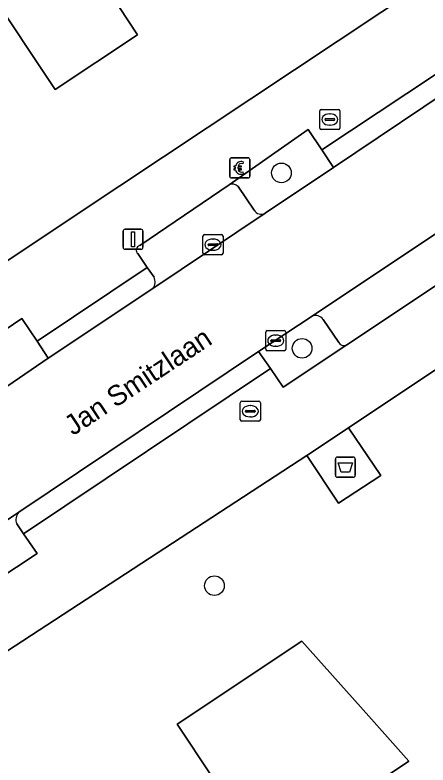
# Model space of a CAD drawing. Extents: x 161347 to 161881, y 382161 to 382804.
# Drawn here: x 161574.44 to 161594.98, y 382587.37 to 382624.69 of the extents above; entities that cross this region are included whole.
import ezdxf

# ---------------------------------------------------------------- set-up
doc = ezdxf.new("R2010")
doc.units = 0
for name, color, linetype in [('IMGEO_Afval_apart_plaats', 7, 'Continuous'), ('IMGEO_Betaalautomaat', 7, 'Continuous'), ('IMGEO_Boom', 7, 'Continuous'), ('IMGEO_Brandkraan', 7, 'Continuous'), ('IMGEO_Erf', 7, 'Continuous'), ('IMGEO_Groenvoorziening', 7, 'Continuous'), ('IMGEO_Kolk', 7, 'Continuous'), ('IMGEO_Lichtmast', 7, 'Continuous'), ('IMGEO_Openbare_ruimte_label', 7, 'Continuous'), ('IMGEO_Pand', 7, 'Continuous'), ('IMGEO_Parkeervlak_open', 7, 'Continuous'), ('IMGEO_Rijbaan_lokaal_open', 7, 'Continuous'), ('IMGEO_Rioolput', 7, 'Continuous'), ('IMGEO_Voetpad_gesloten', 7, 'Continuous'), ('IMGEO_Voetpad_open', 7, 'Continuous')]:
    doc.layers.add(name, color=color, linetype=linetype)

msp = doc.modelspace()

# ---------------------------------------------------------------- linework, layer by layer
at = {"layer": 'IMGEO_Afval_apart_plaats'}
for p, q in [((161590.47, 382602.687), (161591.26, 382602.687)), ((161591.26, 382602.687), (161590.47, 382602.687)), ((161590.37, 382601.787), (161590.37, 382602.587)), ((161590.37, 382602.587), (161590.37, 382601.787)), ((161591.36, 382602.587), (161591.36, 382601.787)), ((161591.36, 382601.787), (161591.36, 382602.587)), ((161591.26, 382601.687), (161590.47, 382601.687)), ((161590.47, 382601.687), (161591.26, 382601.687))]:
    msp.add_line(p, q, dxfattribs=at)
msp.add_lwpolyline([(161590.513, 382602.401), (161591.217, 382602.401), (161591.068, 382601.931), (161590.662, 382601.931), (161590.513, 382602.401)], dxfattribs=at)
for centre, start, end in [((161590.47, 382602.587), 90, 180), ((161590.47, 382602.587), 90, 180), ((161591.26, 382602.587), 0, 90), ((161591.26, 382602.587), 360, 90), ((161590.47, 382601.787), 180, 270), ((161590.47, 382601.787), 180, 270), ((161591.26, 382601.787), 270, 0), ((161591.26, 382601.787), 270, 0)]:
    msp.add_arc(centre, 0.1, start, end, dxfattribs=at)
at = {"layer": 'IMGEO_Betaalautomaat'}
for p, q in [((161585.114, 382616.653), (161585.114, 382617.494)), ((161585.114, 382617.494), (161585.114, 382616.653)), ((161585.189, 382617.577), (161586.03, 382617.577)), ((161586.03, 382617.577), (161585.189, 382617.577)), ((161585.776, 382617.382), (161585.759, 382617.282)), ((161586.113, 382617.503), (161586.113, 382616.662)), ((161586.113, 382616.662), (161586.113, 382617.503)), ((161585.397, 382617.041), (161585.397, 382617.109)), ((161585.518, 382617.109), (161585.518, 382617.041)), ((161585.763, 382616.876), (161585.785, 382616.789)), ((161586.039, 382616.578), (161585.198, 382616.578)), ((161585.198, 382616.578), (161586.039, 382616.578))]:
    msp.add_line(p, q, dxfattribs=at)
for points in [[(161585.397, 382617.109), (161585.328, 382617.109), (161585.328, 382617.178), (161585.407, 382617.178)], [(161585.402, 382616.972), (161585.328, 382616.972), (161585.328, 382617.041), (161585.397, 382617.041)], [(161585.529, 382617.178), (161585.676, 382617.178), (161585.676, 382617.109), (161585.518, 382617.109)], [(161585.518, 382617.041), (161585.676, 382617.041), (161585.676, 382616.972), (161585.532, 382616.972)]]:
    msp.add_lwpolyline(points, dxfattribs=at)
for centre, radius, start, end in [((161585.192, 382617.5), 0.0779, 92.4484, 184.2845), ((161585.192, 382617.5), 0.0779, 92.4484, 184.2845), ((161585.69, 382617.102), 0.293, 73.014, 165.0139), ((161585.696, 382617.115), 0.179, 69.3236, 159.5683), ((161586.036, 382617.5), 0.0779, 2.4484, 94.2845), ((161586.036, 382617.5), 0.0779, 2.4484, 94.2845), ((161585.663, 382617.027), 0.267, 191.8096, 297.0389), ((161585.696, 382617.042), 0.179, 202.7625, 291.8693), ((161585.192, 382616.656), 0.0779, 182.4484, 274.2845), ((161585.192, 382616.656), 0.0779, 182.4484, 274.2845), ((161586.036, 382616.656), 0.0779, 272.4484, 4.2845), ((161586.036, 382616.656), 0.0779, 272.4484, 4.2845)]:
    msp.add_arc(centre, radius, start, end, dxfattribs=at)
at = {"layer": 'IMGEO_Boom'}
for centre in [(161587.688, 382616.829), (161588.717, 382608.1), (161584.357, 382596.29)]:
    msp.add_circle(centre, 0.489, dxfattribs=at)
at = {"layer": 'IMGEO_Brandkraan'}
for p, q in [((161585.637, 382604.544), (161585.637, 382605.396)), ((161585.712, 382605.47), (161586.564, 382605.47)), ((161586.638, 382605.396), (161586.638, 382604.544)), ((161585.896, 382604.964), (161585.896, 382604.976)), ((161586.334, 382604.927), (161585.936, 382604.927)), ((161585.939, 382605.013), (161586.337, 382605.013)), ((161586.125, 382605.25), (161586.15, 382605.25)), ((161586.38, 382604.976), (161586.38, 382604.964)), ((161586.148, 382604.69), (161586.123, 382604.69)), ((161586.564, 382604.47), (161585.712, 382604.47))]:
    msp.add_line(p, q, dxfattribs=at)
for points in [[(161585.637, 382604.544), (161585.637, 382605.396)], [(161585.712, 382605.47), (161586.564, 382605.47)], [(161586.638, 382605.396), (161586.638, 382604.544)], [(161586.564, 382604.47), (161585.712, 382604.47)]]:
    msp.add_lwpolyline(points, dxfattribs=at)
for centre, radius, start, end in [((161585.714, 382605.394), 0.0765, 91.552, 178.448), ((161585.714, 382605.394), 0.0765, 91.552, 178.448), ((161586.562, 382605.394), 0.0765, 1.552, 88.448), ((161586.562, 382605.394), 0.0765, 1.552, 88.448), ((161585.936, 382604.973), 0.0403, 85.8775, 175.7526), ((161585.933, 382604.963), 0.0366, 178.938, 274.7102), ((161586.337, 382604.97), 0.043, 264.8664, 352.4533), ((161586.341, 382604.975), 0.0386, 1.7309, 96.639), ((161585.714, 382604.546), 0.0765, 181.552, 268.448), ((161585.714, 382604.546), 0.0765, 181.552, 268.448), ((161586.562, 382604.546), 0.0765, 271.552, 358.448), ((161586.562, 382604.546), 0.0765, 271.552, 358.448)]:
    msp.add_arc(centre, radius, start, end, dxfattribs=at)
for centre, major_axis, ratio, start_param, end_param in [((161586.124, 382604.97), (-0.387, 0.002), 0.722429, 4.712389, 7.853982), ((161586.149, 382604.97), (-0.39, 0.002), 0.717154, 1.570796, 4.712389)]:
    msp.add_ellipse(centre, major_axis=major_axis, ratio=ratio, start_param=start_param, end_param=end_param, dxfattribs=at)
at = {"layer": 'IMGEO_Erf'}
for points in [[(161467.626, 382669.884), (161470.191, 382665.995), (161471.419, 382664.034), (161492.823, 382629.848), (161494.69, 382626.794), (161500, 382618.564), (161504.473, 382611.274), (161506.241, 382608.392), (161519.986, 382585.99), (161530.719, 382583.477), (161556.508, 382600.797), (161574.373, 382612.676), (161577.471, 382614.736), (161612.276, 382637.879), (161612.356, 382637.679), (161628.452, 382648.518)], [(161665.593, 382585.519), (161669.295, 382588.879), (161675.871, 382594.848), (161676.366, 382595.297), (161679.75, 382598.28), (161653.29, 382627.1), (161642.272, 382638.554), (161626.724, 382627.988), (161591.014, 382604.147), (161592.626, 382601.772), (161590.519, 382600.398), (161588.954, 382602.772), (161572.092, 382591.77), (161539.981, 382570.178)]]:
    msp.add_lwpolyline(points, dxfattribs=at)
for points in [[(161572.304, 382651.615), (161575.985, 382646.088), (161573.679, 382644.552), (161575.924, 382641.181), (161575.266, 382640.743), (161575.975, 382639.677), (161576.632, 382640.114), (161579.388, 382635.978), (161582.16, 382631.816), (161580.992, 382631.038), (161583.334, 382627.521), (161579.633, 382625.056), (161580.533, 382623.704), (161576.439, 382620.977), (161569.66, 382631.156), (161568.37, 382630.297), (161565.599, 382634.459), (161566.822, 382635.347), (161566.041, 382636.521), (161569.021, 382638.506), (161569.803, 382637.333), (161570.96, 382638.104), (161565.14, 382646.843)], [(161586.843, 382582.771), (161585.26, 382585.149), (161584.249, 382586.775), (161582.497, 382589.408), (161588.702, 382593.537), (161592.026, 382589.802), (161594.028, 382587.553)]]:
    msp.add_lwpolyline(points, close=True, dxfattribs=at)
at = {"layer": 'IMGEO_Groenvoorziening'}
for points in [[(161590.272, 382617.093), (161589.689, 382617.973), (161589.012, 382618.995), (161585.081, 382616.229)], [(161586.877, 382614.827), (161590.272, 382617.093)], [(161585.528, 382616.145), (161586.327, 382614.968)], [(161589.217, 382609.696), (161586.553, 382607.94), (161587.144, 382607.09), (161587.772, 382606.172), (161590.935, 382608.278)], [(161590.54, 382608.383), (161589.758, 382609.534)]]:
    msp.add_lwpolyline(points, dxfattribs=at)
msp.add_lwpolyline([(161576.086, 382607.606), (161575.54, 382608.454), (161574.77, 382609.585), (161571.539, 382607.403), (161572.313, 382606.29), (161572.895, 382605.439)], close=True, dxfattribs=at)
for centre, radius, start, end in [((161585.25, 382615.898), 0.371, 41.6099, 117.1043), ((161586.677, 382615.189), 0.414, 212.2674, 298.9748), ((161589.39, 382609.291), 0.441, 33.4839, 113.1759), ((161590.789, 382608.525), 0.287, 209.7009, 300.5265)]:
    msp.add_arc(centre, radius, start, end, dxfattribs=at)
at = {"layer": 'IMGEO_Kolk'}
for p, q in [((161583.78, 382612.832), (161583.78, 382613.684)), ((161583.855, 382613.758), (161584.707, 382613.758)), ((161584.268, 382613.538), (161584.293, 382613.538)), ((161584.781, 382613.684), (161584.781, 382612.832)), ((161584.039, 382613.252), (161584.039, 382613.264)), ((161584.477, 382613.215), (161584.079, 382613.215)), ((161584.082, 382613.301), (161584.48, 382613.301)), ((161584.523, 382613.264), (161584.523, 382613.252)), ((161584.707, 382612.758), (161583.855, 382612.758)), ((161584.291, 382612.978), (161584.266, 382612.978)), ((161586.903, 382608.055), (161586.903, 382608.907)), ((161586.978, 382608.981), (161587.83, 382608.981)), ((161587.391, 382608.761), (161587.416, 382608.761)), ((161587.904, 382608.907), (161587.904, 382608.055)), ((161587.162, 382608.475), (161587.162, 382608.487)), ((161587.6, 382608.438), (161587.202, 382608.438)), ((161587.205, 382608.524), (161587.603, 382608.524)), ((161587.646, 382608.487), (161587.646, 382608.475)), ((161587.83, 382607.981), (161586.978, 382607.981)), ((161587.414, 382608.201), (161587.389, 382608.201))]:
    msp.add_line(p, q, dxfattribs=at)
for points in [[(161583.78, 382612.832), (161583.78, 382613.684)], [(161583.855, 382613.758), (161584.707, 382613.758)], [(161584.781, 382613.684), (161584.781, 382612.832)], [(161584.707, 382612.758), (161583.855, 382612.758)], [(161586.903, 382608.055), (161586.903, 382608.907)], [(161586.978, 382608.981), (161587.83, 382608.981)], [(161587.904, 382608.907), (161587.904, 382608.055)], [(161587.83, 382607.981), (161586.978, 382607.981)]]:
    msp.add_lwpolyline(points, dxfattribs=at)
for centre, radius, start, end in [((161583.857, 382613.682), 0.0765, 91.552, 178.448), ((161583.857, 382613.682), 0.0765, 91.552, 178.448), ((161584.705, 382613.682), 0.0765, 1.552, 88.448), ((161584.705, 382613.682), 0.0765, 1.552, 88.448), ((161584.079, 382613.261), 0.0403, 85.8775, 175.7526), ((161584.076, 382613.251), 0.0366, 178.938, 274.7102), ((161584.48, 382613.258), 0.043, 264.8664, 352.4533), ((161584.484, 382613.263), 0.0386, 1.7309, 96.639), ((161583.857, 382612.834), 0.0765, 181.552, 268.448), ((161583.857, 382612.834), 0.0765, 181.552, 268.448), ((161584.705, 382612.834), 0.0765, 271.552, 358.448), ((161584.705, 382612.834), 0.0765, 271.552, 358.448), ((161586.98, 382608.905), 0.0765, 91.552, 178.448), ((161586.98, 382608.905), 0.0765, 91.552, 178.448), ((161587.828, 382608.905), 0.0765, 1.552, 88.448), ((161587.828, 382608.905), 0.0765, 1.552, 88.448), ((161587.202, 382608.484), 0.0403, 85.8775, 175.7526), ((161587.199, 382608.474), 0.0366, 178.938, 274.7102), ((161587.603, 382608.481), 0.043, 264.8664, 352.4533), ((161587.607, 382608.486), 0.0386, 1.7309, 96.639), ((161586.98, 382608.057), 0.0765, 181.552, 268.448), ((161586.98, 382608.057), 0.0765, 181.552, 268.448), ((161587.828, 382608.057), 0.0765, 271.552, 358.448), ((161587.828, 382608.057), 0.0765, 271.552, 358.448)]:
    msp.add_arc(centre, radius, start, end, dxfattribs=at)
for centre, major_axis, ratio, start_param, end_param in [((161584.267, 382613.258), (-0.387, 0.002), 0.722429, 4.712389, 7.853982), ((161584.292, 382613.258), (-0.39, 0.002), 0.717154, 1.570796, 4.712389), ((161587.39, 382608.481), (-0.387, 0.002), 0.722429, 4.712389, 7.853982), ((161587.415, 382608.481), (-0.39, 0.002), 0.717154, 1.570796, 4.712389)]:
    msp.add_ellipse(centre, major_axis=major_axis, ratio=ratio, start_param=start_param, end_param=end_param, dxfattribs=at)
at = {"layer": 'IMGEO_Lichtmast'}
for p, q in [((161579.812, 382613.127), (161579.812, 382613.927)), ((161579.812, 382613.927), (161579.812, 382613.127)), ((161579.912, 382614.027), (161580.702, 382614.027)), ((161580.702, 382614.027), (161579.912, 382614.027)), ((161580.802, 382613.927), (161580.802, 382613.127)), ((161580.802, 382613.127), (161580.802, 382613.927)), ((161580.702, 382613.027), (161579.912, 382613.027)), ((161579.912, 382613.027), (161580.702, 382613.027))]:
    msp.add_line(p, q, dxfattribs=at)
msp.add_lwpolyline([(161580.232, 382613.902), (161580.382, 382613.902), (161580.382, 382613.152), (161580.232, 382613.152), (161580.232, 382613.902)], dxfattribs=at)
for centre, start, end in [((161579.912, 382613.927), 90, 180), ((161579.912, 382613.927), 90, 180), ((161580.702, 382613.927), 0, 90), ((161580.702, 382613.927), 360, 90), ((161579.912, 382613.127), 180, 270), ((161579.912, 382613.127), 180, 270), ((161580.702, 382613.127), 270, 0), ((161580.702, 382613.127), 270, 0)]:
    msp.add_arc(centre, 0.1, start, end, dxfattribs=at)
at = {"layer": 'IMGEO_Pand'}
for points in [[(161565.599, 382634.459), (161568.37, 382630.297), (161569.66, 382631.156), (161576.439, 382620.977), (161580.533, 382623.704), (161579.633, 382625.056), (161583.334, 382627.521), (161580.992, 382631.038), (161582.16, 382631.816), (161579.388, 382635.978), (161576.632, 382640.114), (161575.975, 382639.677), (161575.266, 382640.743), (161575.924, 382641.181), (161573.679, 382644.552), (161575.985, 382646.088), (161572.304, 382651.615), (161565.14, 382646.843), (161570.96, 382638.104), (161569.803, 382637.333), (161569.021, 382638.506), (161566.041, 382636.521), (161566.822, 382635.347)], [(161585.26, 382585.149), (161586.843, 382582.771), (161594.028, 382587.553), (161592.026, 382589.802), (161588.702, 382593.537), (161582.497, 382589.408), (161584.249, 382586.775)]]:
    msp.add_lwpolyline(points, close=True, dxfattribs=at)
at = {"layer": 'IMGEO_Parkeervlak_open'}
for points in [[(161604.234, 382619.763), (161598.787, 382616.092), (161589.217, 382609.696)], [(161590.935, 382608.278), (161604.861, 382617.547)], [(161585.081, 382616.229), (161580.638, 382613.21)], [(161586.327, 382614.968), (161585.528, 382616.145)], [(161581.294, 382611.082), (161586.877, 382614.827)], [(161580.541, 382612.811), (161581.017, 382612.127), (161581.354, 382611.643)], [(161589.758, 382609.534), (161590.54, 382608.383)], [(161574.626, 382599.941), (161568.848, 382596.061)], [(161574.859, 382598.875), (161574.524, 382599.371)], [(161569.4, 382595.88), (161570.33, 382594.467), (161575.536, 382597.897), (161574.859, 382598.875)]]:
    msp.add_lwpolyline(points, dxfattribs=at)
for centre, radius, start, end in [((161585.25, 382615.898), 0.371, 41.6099, 117.1043), ((161586.677, 382615.189), 0.414, 212.2674, 298.9748), ((161580.706, 382612.982), 0.238, 106.6632, 226.0088), ((161580.859, 382611.412), 0.546, 322.8092, 24.9815), ((161589.39, 382609.291), 0.441, 33.4839, 113.1759), ((161590.789, 382608.525), 0.287, 209.7009, 300.5265), ((161575.002, 382599.58), 0.522, 136.142, 203.5669)]:
    msp.add_arc(centre, radius, start, end, dxfattribs=at)
at = {"layer": 'IMGEO_Rijbaan_lokaal_open'}
for points in [[(161629.984, 382643.685), (161629.082, 382643.096), (161623.606, 382639.398), (161620.915, 382637.62), (161615.453, 382633.951), (161609.534, 382629.982), (161606.959, 382628.256), (161596.988, 382621.601), (161590.272, 382617.093), (161586.877, 382614.827), (161581.294, 382611.082), (161576.086, 382607.606), (161572.895, 382605.439), (161568.174, 382602.328), (161567.876, 382602.127), (161562.92, 382598.78), (161558.888, 382596.045), (161556.499, 382594.479), (161546.269, 382587.605), (161541.693, 382584.498)], [(161551.753, 382584.552), (161566.828, 382594.718), (161568.848, 382596.061), (161574.626, 382599.941), (161586.553, 382607.94), (161589.217, 382609.696), (161598.787, 382616.092), (161604.234, 382619.763)]]:
    msp.add_lwpolyline(points, dxfattribs=at)
at = {"layer": 'IMGEO_Rioolput'}
for p, q in [((161589.592, 382619.06), (161589.592, 382619.912)), ((161589.667, 382619.986), (161590.519, 382619.986)), ((161590.593, 382619.912), (161590.593, 382619.06)), ((161589.851, 382619.48), (161589.851, 382619.492)), ((161589.894, 382619.529), (161590.292, 382619.529)), ((161590.08, 382619.766), (161590.105, 382619.766)), ((161590.335, 382619.492), (161590.335, 382619.48)), ((161590.289, 382619.443), (161589.891, 382619.443)), ((161590.103, 382619.206), (161590.078, 382619.206)), ((161590.519, 382618.986), (161589.667, 382618.986))]:
    msp.add_line(p, q, dxfattribs=at)
for points in [[(161589.592, 382619.06), (161589.592, 382619.912)], [(161589.667, 382619.986), (161590.519, 382619.986)], [(161590.593, 382619.912), (161590.593, 382619.06)], [(161590.519, 382618.986), (161589.667, 382618.986)]]:
    msp.add_lwpolyline(points, dxfattribs=at)
for centre, radius, start, end in [((161589.669, 382619.91), 0.0765, 91.552, 178.448), ((161589.669, 382619.91), 0.0765, 91.552, 178.448), ((161590.517, 382619.91), 0.0765, 1.552, 88.448), ((161590.517, 382619.91), 0.0765, 1.552, 88.448), ((161589.891, 382619.489), 0.0403, 85.8775, 175.7526), ((161589.888, 382619.479), 0.0366, 178.938, 274.7102), ((161590.292, 382619.486), 0.043, 264.8664, 352.4533), ((161590.296, 382619.491), 0.0386, 1.7309, 96.639), ((161589.669, 382619.062), 0.0765, 181.552, 268.448), ((161589.669, 382619.062), 0.0765, 181.552, 268.448), ((161590.517, 382619.062), 0.0765, 271.552, 358.448), ((161590.517, 382619.062), 0.0765, 271.552, 358.448)]:
    msp.add_arc(centre, radius, start, end, dxfattribs=at)
for centre, major_axis, ratio, start_param, end_param in [((161590.079, 382619.486), (-0.387, 0.002), 0.722429, 4.712389, 7.853982), ((161590.104, 382619.486), (-0.39, 0.002), 0.717154, 1.570796, 4.712389)]:
    msp.add_ellipse(centre, major_axis=major_axis, ratio=ratio, start_param=start_param, end_param=end_param, dxfattribs=at)
at = {"layer": 'IMGEO_Voetpad_gesloten'}
msp.add_lwpolyline([(161591.014, 382604.147), (161588.954, 382602.772), (161590.519, 382600.398), (161592.626, 382601.772)], close=True, dxfattribs=at)
at = {"layer": 'IMGEO_Voetpad_open'}
for points in [[(161633.531, 382651.891), (161632.827, 382651.824), (161628.452, 382648.518), (161612.356, 382637.679), (161612.276, 382637.879), (161577.471, 382614.736), (161574.373, 382612.676), (161556.508, 382600.797), (161530.719, 382583.477), (161519.986, 382585.99), (161514.869, 382582.227), (161517.208, 382578.534)], [(161636.042, 382640.978), (161637.263, 382639.172), (161635.101, 382637.794), (161625.023, 382631.053), (161624.388, 382631.946), (161620.048, 382629.035), (161620.647, 382628.172), (161617.655, 382626.128), (161608.366, 382619.905), (161604.861, 382617.547), (161590.935, 382608.278), (161587.772, 382606.172), (161587.144, 382607.09), (161574.859, 382598.875), (161575.536, 382597.897), (161570.33, 382594.467), (161567.696, 382592.692), (161553.267, 382582.995), (161550.455, 382581.099), (161540.9, 382574.692), (161538.305, 382572.954), (161537.081, 382574.722), (161535.802, 382573.856), (161531.835, 382571.172)], [(161539.981, 382570.178), (161572.092, 382591.77), (161588.954, 382602.772), (161591.014, 382604.147), (161626.724, 382627.988), (161642.272, 382638.554), (161645.871, 382640.073)], [(161580.638, 382613.21), (161585.081, 382616.229), (161589.012, 382618.995), (161589.689, 382617.973), (161596.732, 382622.631), (161596.273, 382623.316)], [(161597.04, 382622.17), (161596.732, 382622.631), (161589.689, 382617.973), (161590.272, 382617.093), (161596.988, 382621.601)], [(161540.41, 382586.303), (161541.067, 382585.364), (161546.022, 382588.682), (161545.38, 382589.578), (161555.001, 382596.043), (161557.659, 382597.826), (161558.295, 382596.893), (161562.64, 382599.822), (161562.017, 382600.769), (161566.681, 382603.875), (161567.302, 382602.987), (161572.313, 382606.29), (161571.539, 382607.403), (161574.77, 382609.585), (161575.54, 382608.454), (161581.017, 382612.127), (161580.541, 382612.811)], [(161581.354, 382611.643), (161581.017, 382612.127), (161575.54, 382608.454), (161576.086, 382607.606), (161581.294, 382611.082)], [(161587.144, 382607.09), (161586.553, 382607.94), (161574.626, 382599.941)], [(161574.524, 382599.371), (161574.859, 382598.875), (161587.144, 382607.09)]]:
    msp.add_lwpolyline(points, dxfattribs=at)
for centre, radius, start, end in [((161580.706, 382612.982), 0.238, 106.6632, 226.0088), ((161580.859, 382611.412), 0.546, 322.8092, 24.9815), ((161575.002, 382599.58), 0.522, 136.142, 203.5669)]:
    msp.add_arc(centre, radius, start, end, dxfattribs=at)

# ---------------------------------------------------------------- texts
at = {"layer": 'IMGEO_Openbare_ruimte_label'}
msp.add_text('Jan Smitzlaan', height=1, rotation=33.4994, dxfattribs=at).set_placement((161577.316, 382603.725))

doc.saveas('drawing.dxf')
